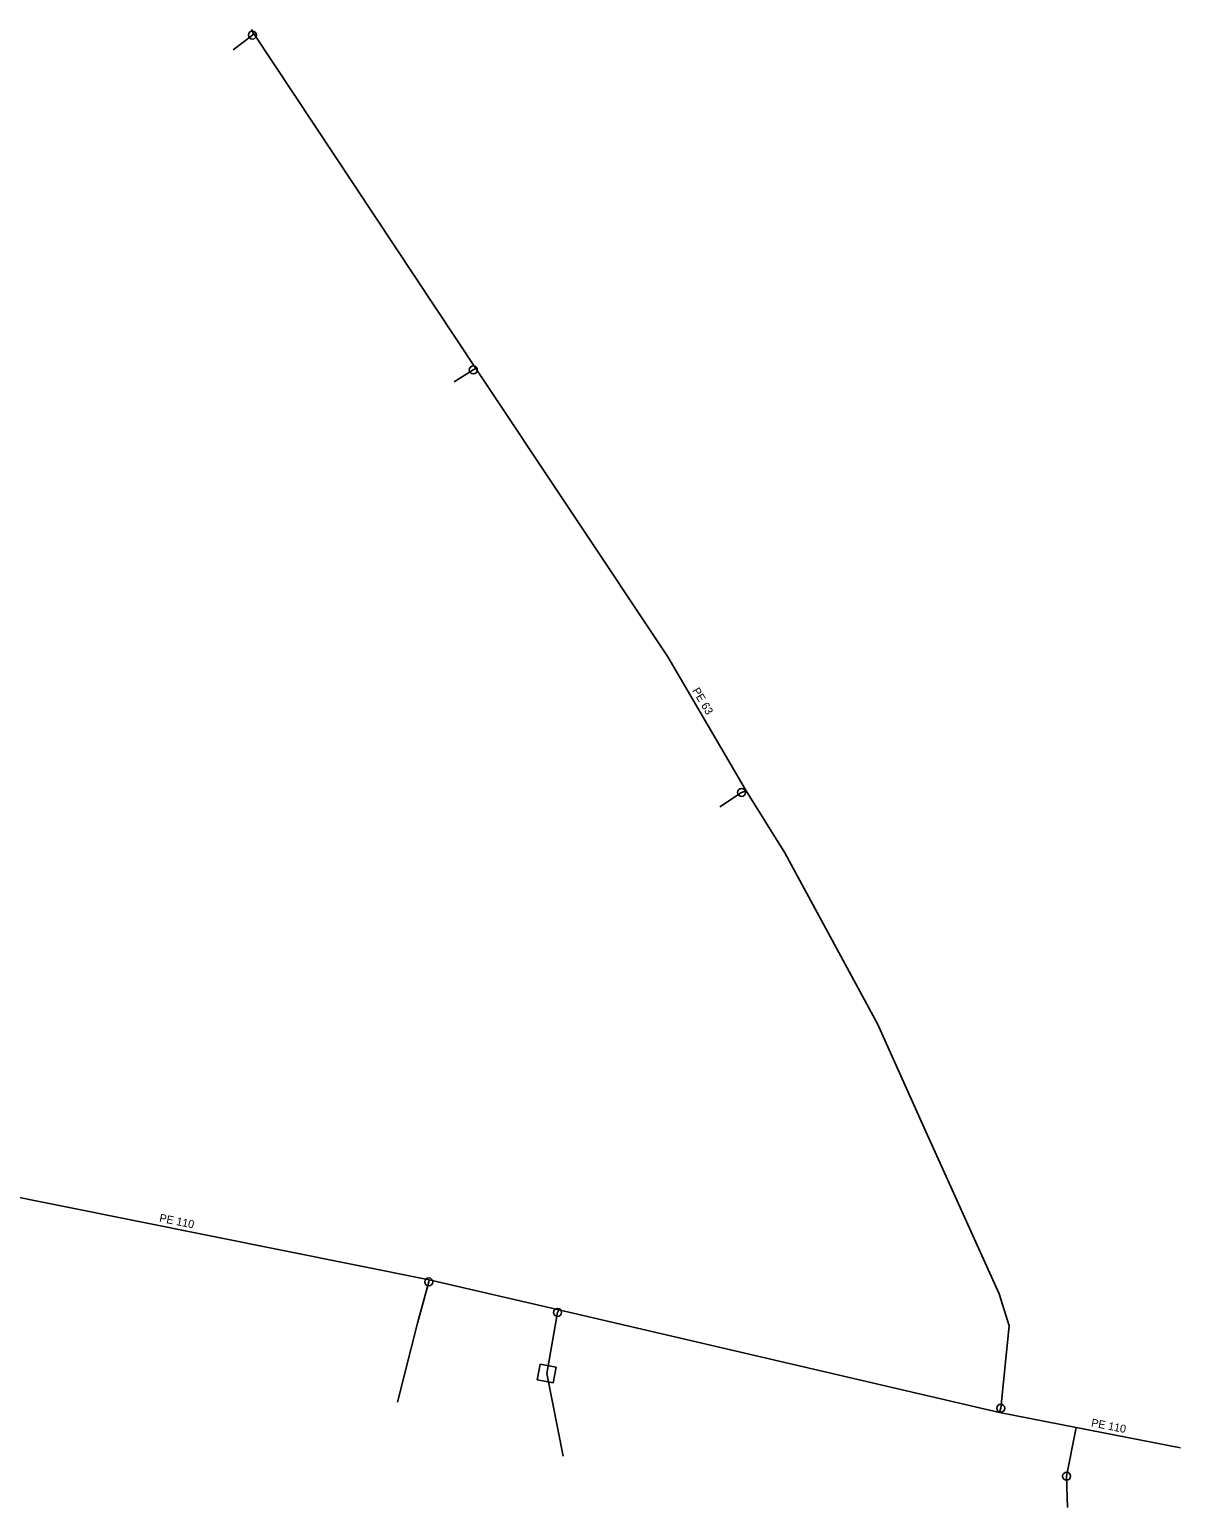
# Model space of a CAD drawing. Extents: x -681947 to -681511, y -1163527 to -1163073.
# Drawn here: x -681664 to -681592.2, y -1163469.7 to -1163377.4 of the extents above; entities that cross this region are included whole.
import ezdxf

# ---------------------------------------------------------------- set-up
doc = ezdxf.new("R2010")
doc.units = 0
for name, color, linetype in [('Popis vodovodních řadů', 7, 'Continuous'), ('Vod přípojky-voda pitná', 7, 'Continuous'), ('Vodovodní řad', 7, 'Continuous'), ('Vodovodní šachty', 7, 'Continuous'), ('Vodovodní šoupata', 7, 'Continuous')]:
    doc.layers.add(name, color=color, linetype=linetype)

msp = doc.modelspace()

# ---------------------------------------------------------------- linework, layer by layer
at = {"layer": 'Vod přípojky-voda pitná'}
for points in [[(-681650.04, -1163377.64), (-681650.1, -1163377.77), (-681651.3, -1163378.68)], [(-681636.16, -1163398.59), (-681636.31, -1163398.68), (-681637.5, -1163399.43)], [(-681619.28, -1163424.96), (-681619.56, -1163425.07), (-681620.92, -1163425.97)], [(-681639.07, -1163455.52), (-681639.09, -1163455.64), (-681639.8, -1163458.21)], [(-681630.97, -1163457.38), (-681631.05, -1163457.55), (-681631.73, -1163461.36)], [(-681639.8, -1163458.21), (-681641.05, -1163463.15)], [(-681631.73, -1163461.36), (-681630.71, -1163466.53)], [(-681598.68, -1163464.74), (-681599.27, -1163467.78), (-681599.22, -1163469.73)]]:
    msp.add_lwpolyline(points, dxfattribs=at)
at = {"layer": 'Vodovodní řad'}
for points in [[(-681603.38, -1163463.53), (-681602.86, -1163458.38), (-681603.47, -1163456.39), (-681608.17, -1163446.01), (-681611.08, -1163439.53), (-681616.85, -1163428.85), (-681619.28, -1163424.96), (-681624.17, -1163416.61), (-681636.16, -1163398.59), (-681650.04, -1163377.64), (-681650.15, -1163377.42)], [(-681708.67, -1163441.09), (-681691.14, -1163444.83), (-681685.63, -1163445.99), (-681682.3, -1163446.63), (-681666.54, -1163450), (-681639.07, -1163455.52), (-681630.97, -1163457.38), (-681603.46, -1163463.79)], [(-681603.46, -1163463.79), (-681603.38, -1163463.53)], [(-681603.46, -1163463.79), (-681598.68, -1163464.74), (-681592.161, -1163466.015)]]:
    msp.add_lwpolyline(points, dxfattribs=at)
at = {"layer": 'Vodovodní šachty'}
for p, q in [((-681632.127, -1163460.775), (-681632.315, -1163461.757)), ((-681631.145, -1163460.963), (-681632.127, -1163460.775)), ((-681631.333, -1163461.945), (-681631.145, -1163460.963)), ((-681632.315, -1163461.757), (-681631.333, -1163461.945))]:
    msp.add_line(p, q, dxfattribs=at)
at = {"layer": 'Vodovodní šoupata'}
for centre in [(-681650.1, -1163377.77), (-681636.31, -1163398.68), (-681619.56, -1163425.07), (-681639.09, -1163455.64), (-681631.05, -1163457.55), (-681603.38, -1163463.53), (-681599.27, -1163467.78)]:
    msp.add_circle(centre, 0.25, dxfattribs=at)

# ---------------------------------------------------------------- texts
at = {"layer": 'Popis vodovodních řadů'}
for s, rotation, p in [('PE 63', 300.35447, (-681622.656, -1163418.7)), ('PE 110', 348.63793, (-681655.944, -1163451.874)), ('PE 110', 348.93094, (-681597.764, -1163464.665))]:
    msp.add_text(s, height=0.5, rotation=rotation, dxfattribs=at).set_placement(p)

doc.saveas('drawing.dxf')
